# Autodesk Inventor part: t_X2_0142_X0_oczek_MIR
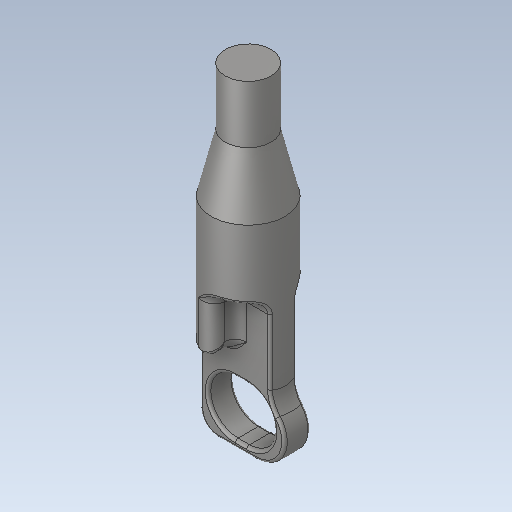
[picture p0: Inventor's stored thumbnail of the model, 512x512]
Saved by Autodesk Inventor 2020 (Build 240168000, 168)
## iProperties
Created: 2015-11
Part Number: t_X2_0142_X0_oczek_MIR
Material: Ogólny
Document SubType Name: Modeling
Designer: Tomasz
Density: 1 g/cm^3
Appearance: Domyślna
Sending System: SolidWorks 2017
Last Author: Tomasz
Last Saved: 2017-10-01
Author: Tomasz
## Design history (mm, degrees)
feature "Imported1"
node "Bryła1"
